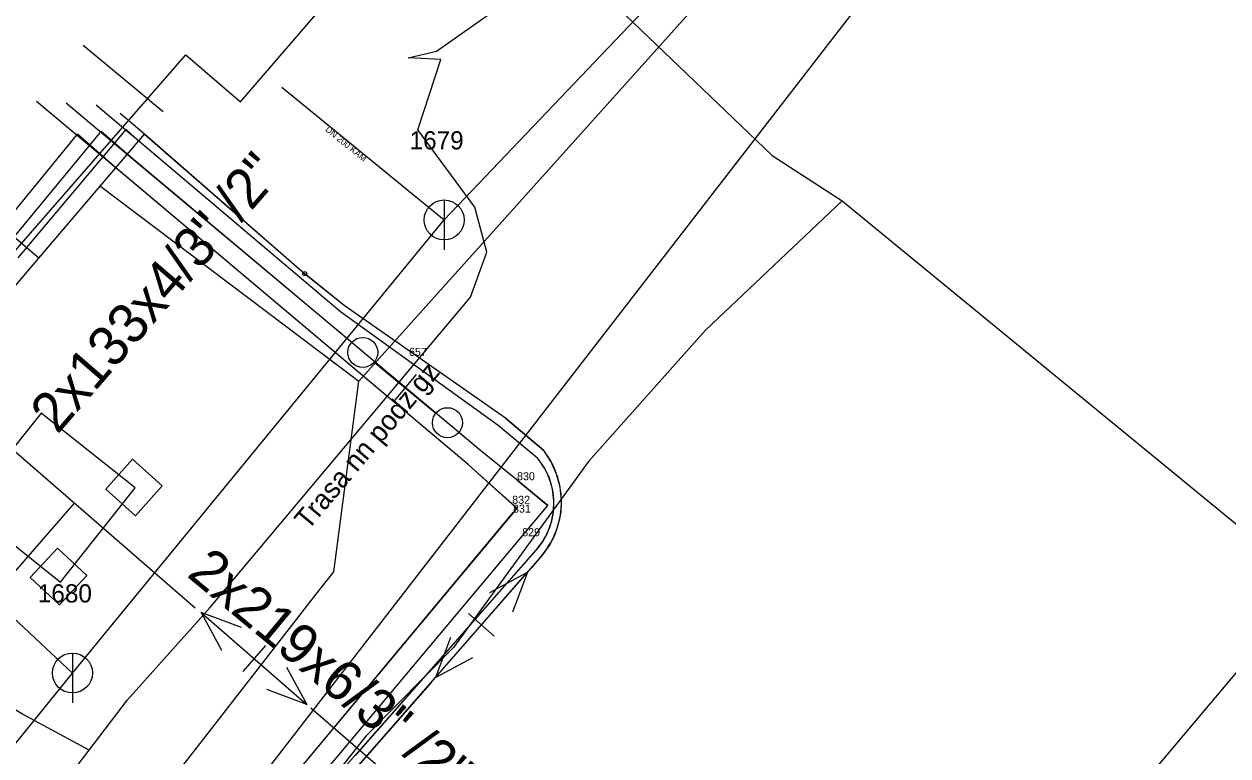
# Model space of a CAD drawing. Extents: x -494395 to -49419, y -1126982 to -112683.
# Drawn here: x -494321.11 to -494291.02, y -1126840.42 to -1126822.11 of the extents above; entities that cross this region are included whole.
import ezdxf

# ---------------------------------------------------------------- set-up
doc = ezdxf.new("R2010")
doc.units = 0
for name, color, linetype in [('Vrstva 1', 7, 'Continuous'), ('Vrstva 15', 7, 'Continuous'), ('Vrstva 17', 7, 'Continuous'), ('Vrstva 19', 7, 'Continuous'), ('Vrstva 20', 7, 'Continuous'), ('Vrstva 35', 7, 'Continuous'), ('Vrstva 45', 7, 'Continuous'), ('Vrstva 48', 7, 'Continuous'), ('Vrstva 49', 7, 'Continuous'), ('Vrstva 5', 7, 'Continuous'), ('Vrstva 9', 7, 'Continuous')]:
    doc.layers.add(name, color=color, linetype=linetype)

msp = doc.modelspace()

# ---------------------------------------------------------------- linework, layer by layer
at = {"layer": 'Vrstva 1'}
msp.add_line((-494319.22, -1126826.15), (-494312.74, -1126831.04), dxfattribs=at)
msp.add_lwpolyline([(-494360.93, -1126825.46), (-494336.61, -1126847.07), (-494335.52, -1126848.04), (-494331.63, -1126851.49), (-494328.43, -1126854.34), (-494326.87, -1126852.55), (-494322.66, -1126847.73), (-494316.57, -1126839.92), (-494313.81, -1126836.37), (-494313.37, -1126835.81), (-494312.74, -1126831.04), (-494296.98, -1126813.46), (-494295.26, -1126811.1), (-494294.71, -1126810.42), (-494294.273, -1126809.878)], dxfattribs=at)
at = {"layer": 'Vrstva 15'}
for p, q in [((-494310.61, -1126827.011), (-494304.84, -1126820.951)), ((-494314.667, -1126823.687), (-494310.61, -1126827.011)), ((-494319.9, -1126838.341), (-494310.61, -1126827.011)), ((-494323.18, -1126835.277), (-494319.9, -1126838.341)), ((-494334.61, -1126856.561), (-494319.9, -1126838.341))]:
    msp.add_line(p, q, dxfattribs=at)
at = {"layer": 'Vrstva 17'}
for p, q in [((-494310.61, -1126826.511), (-494310.61, -1126827.761)), ((-494319.9, -1126837.841), (-494319.9, -1126839.091))]:
    msp.add_line(p, q, dxfattribs=at)
for centre in [(-494310.61, -1126827.011), (-494319.9, -1126838.341)]:
    msp.add_circle(centre, 0.5, dxfattribs=at)
at = {"layer": 'Vrstva 20'}
for points in [[(-494292.524, -1126811.151), (-494292.619, -1126811.279), (-494299.712, -1126820.924), (-494325.277, -1126853.999), (-494328.623, -1126858.84)], [(-494316.901, -1126869.31), (-494312.976, -1126864.212), (-494296.263, -1126844.814), (-494282.714, -1126828.712), (-494277.399, -1126822.165)]]:
    msp.add_lwpolyline(points, dxfattribs=at)
at = {"layer": 'Vrstva 35'}
for points in [[(-494311.3, -1126816.88), (-494302.41, -1126825.4), (-494300.66, -1126826.53), (-494287.83, -1126837.07), (-494286.16, -1126837.53), (-494283.18, -1126840.13)], [(-494300.66, -1126826.53), (-494304.08, -1126829.77), (-494307, -1126833.05), (-494310.38, -1126837.7), (-494312.57, -1126839.92), (-494316.3, -1126844.63), (-494317.42, -1126846.17), (-494319.02, -1126847.69), (-494327.08, -1126857.66), (-494327.96, -1126857.89), (-494330.7, -1126861.76), (-494332.02, -1126864.51), (-494334.7, -1126868.68), (-494331.75, -1126870.74), (-494343.19, -1126889.21), (-494346.12, -1126887.28)]]:
    msp.add_lwpolyline(points, dxfattribs=at)
at = {"layer": 'Vrstva 45'}
for p, q in [((-494315.7, -1126824.06), (-494311.17, -1126818.8)), ((-494320.74, -1126827.97), (-494328.91, -1126821.01)), ((-494317.07, -1126822.88), (-494315.7, -1126824.06)), ((-494322.43, -1126828.11), (-494319.77, -1126824.87)), ((-494321.86, -1126828.04), (-494319.18, -1126824.8)), ((-494321.26, -1126827.96), (-494318.56, -1126824.75)), ((-494320.74, -1126827.97), (-494318.1, -1126824.87)), ((-494318.87, -1126825.66), (-494319.77, -1126824.87)), ((-494318.48, -1126825.41), (-494319.18, -1126824.8)), ((-494318.24, -1126825.04), (-494318.56, -1126824.75)), ((-494318.1, -1126824.87), (-494314.1, -1126828.35)), ((-494314.1, -1126828.36), (-494318.1, -1126824.87)), ((-494318.09, -1126824.87), (-494318.09, -1126824.87)), ((-494313.2, -1126829.31), (-494318.24, -1126825.04)), ((-494318.24, -1126825.04), (-494318.24, -1126825.04)), ((-494313.2, -1126829.31), (-494318.24, -1126825.04)), ((-494318.52, -1126825.38), (-494318.52, -1126825.38)), ((-494312.96, -1126830.04), (-494318.52, -1126825.38)), ((-494309.74, -1126832.74), (-494318.48, -1126825.41)), ((-494310.01, -1126833.13), (-494318.87, -1126825.66)), ((-494318.81, -1126825.72), (-494318.81, -1126825.72)), ((-494310.01, -1126833.13), (-494318.81, -1126825.72)), ((-494329.83, -1126838.63), (-494320.74, -1126827.97)), ((-494313.11, -1126829.15), (-494314.1, -1126828.35)), ((-494314.1, -1126828.35), (-494314.1, -1126828.35)), ((-494313.11, -1126829.15), (-494314.1, -1126828.36)), ((-494309.26, -1126832.15), (-494313.2, -1126829.31)), ((-494313.2, -1126829.31), (-494313.2, -1126829.31)), ((-494309.26, -1126832.15), (-494313.2, -1126829.31)), ((-494309.08, -1126831.97), (-494313.11, -1126829.15)), ((-494313.11, -1126829.15), (-494313.11, -1126829.15)), ((-494309.08, -1126831.97), (-494313.11, -1126829.15)), ((-494312.357, -1126830.564), (-494310.817, -1126831.84)), ((-494311.49, -1126830.41), (-494311.49, -1126830.41)), ((-494311.312, -1126830.872), (-494311.861, -1126831.534)), ((-494323.07, -1126831.3), (-494316.83, -1126836.71)), ((-494309.08, -1126831.97), (-494308.12, -1126832.78)), ((-494309.08, -1126831.97), (-494309.08, -1126831.97)), ((-494308.12, -1126832.78), (-494309.08, -1126831.97)), ((-494309.74, -1126832.74), (-494310.2, -1126832.36)), ((-494308.27, -1126832.98), (-494309.26, -1126832.15)), ((-494309.26, -1126832.15), (-494309.26, -1126832.15)), ((-494308.27, -1126832.98), (-494309.26, -1126832.15)), ((-494309.74, -1126832.74), (-494309.74, -1126832.74)), ((-494308.79, -1126833.52), (-494309.74, -1126832.74)), ((-494308.79, -1126833.52), (-494309.74, -1126832.74)), ((-494308.27, -1126832.98), (-494308.27, -1126832.98)), ((-494308.1, -1126833.21), (-494308.27, -1126832.98)), ((-494308.12, -1126832.78), (-494308.12, -1126832.78)), ((-494307.94, -1126833.06), (-494308.12, -1126832.78)), ((-494310.01, -1126833.13), (-494310.01, -1126833.13)), ((-494308.91, -1126834.11), (-494310.01, -1126833.13)), ((-494308.91, -1126834.12), (-494310.01, -1126833.13)), ((-494307.98, -1126833.47), (-494308.1, -1126833.21)), ((-494307.8, -1126833.37), (-494307.94, -1126833.06)), ((-494308.79, -1126833.52), (-494308.79, -1126833.52)), ((-494308.79, -1126833.52), (-494308.02, -1126834.15)), ((-494308.02, -1126834.15), (-494308.79, -1126833.52)), ((-494307.9, -1126833.74), (-494307.98, -1126833.47)), ((-494307.71, -1126833.69), (-494307.8, -1126833.37)), ((-494307.87, -1126834.03), (-494307.9, -1126833.74)), ((-494307.68, -1126834.03), (-494307.71, -1126833.69)), ((-494335.11, -1126851.71), (-494319.85, -1126834.09)), ((-494308.91, -1126834.11), (-494308.91, -1126834.11)), ((-494308.91, -1126834.11), (-494308.79, -1126834.22)), ((-494308.79, -1126834.22), (-494308.91, -1126834.12)), ((-494308.89, -1126834.33), (-494308.79, -1126834.22)), ((-494308.89, -1126834.34), (-494308.79, -1126834.22)), ((-494308.79, -1126834.22), (-494308.79, -1126834.22)), ((-494308.66, -1126834.92), (-494308.02, -1126834.15)), ((-494308.66, -1126834.92), (-494308.02, -1126834.15)), ((-494308.02, -1126834.15), (-494308.02, -1126834.15)), ((-494307.88, -1126834.3), (-494307.87, -1126834.03)), ((-494307.87, -1126834.03), (-494307.87, -1126834.03)), ((-494307.69, -1126834.32), (-494307.68, -1126834.03)), ((-494307.68, -1126834.03), (-494307.68, -1126834.03)), ((-494316.57, -1126843.56), (-494308.89, -1126834.33)), ((-494316.57, -1126843.56), (-494308.89, -1126834.34)), ((-494308.89, -1126834.33), (-494308.89, -1126834.33)), ((-494307.93, -1126834.56), (-494307.88, -1126834.3)), ((-494307.75, -1126834.61), (-494307.69, -1126834.32)), ((-494320.29, -1126834.6), (-494320.29, -1126834.6)), ((-494308.04, -1126834.86), (-494308.02, -1126834.82)), ((-494308.02, -1126834.82), (-494307.93, -1126834.56)), ((-494307.84, -1126834.88), (-494307.75, -1126834.61)), ((-494316.37, -1126844.12), (-494308.66, -1126834.92)), ((-494316.37, -1126844.12), (-494308.66, -1126834.92)), ((-494308.66, -1126834.92), (-494308.66, -1126834.92)), ((-494308.31, -1126835.27), (-494308.15, -1126835.06)), ((-494308.15, -1126835.06), (-494308.04, -1126834.86)), ((-494307.98, -1126835.15), (-494307.84, -1126834.88)), ((-494314.68, -1126842.49), (-494308.31, -1126835.27)), ((-494312.93, -1126840.85), (-494308.15, -1126835.39)), ((-494312.83, -1126840.4), (-494308.31, -1126835.27)), ((-494308.15, -1126835.38), (-494308.43, -1126835.71)), ((-494308.31, -1126835.27), (-494308.31, -1126835.27)), ((-494308.15, -1126835.39), (-494307.98, -1126835.15)), ((-494308.15, -1126835.38), (-494308.15, -1126835.38)), ((-494310.831, -1126838.457), (-494308.53, -1126835.82)), ((-494316.68, -1126836.832), (-494314.04, -1126839.13)), ((-494310.003, -1126836.857), (-494309.358, -1126837.422)), ((-494316.74, -1126837.01), (-494316.74, -1126837.01)), ((-494315.077, -1126837.656), (-494315.642, -1126838.306)), ((-494310.93, -1126838.57), (-494317.14, -1126845.66)), ((-494313.94, -1126839.21), (-494307.12, -1126845.12))]:
    msp.add_line(p, q, dxfattribs=at)
for points in [[(-494323.83, -1126830.64), (-494317.07, -1126822.88)], [(-494309.47, -1126836.327), (-494308.53, -1126835.82), (-494308.905, -1126836.819)], [(-494315.679, -1126837.205), (-494316.68, -1126836.832), (-494316.172, -1126837.771)], [(-494310.455, -1126837.456), (-494310.831, -1126838.457), (-494309.891, -1126837.95)], [(-494314.548, -1126838.191), (-494314.04, -1126839.13), (-494315.04, -1126838.756)]]:
    msp.add_lwpolyline(points, dxfattribs=at)
for centre, radius in [((-494314.096, -1126828.354), 0.05), ((-494312.644, -1126830.325), 0.375), ((-494310.528, -1126832.081), 0.375)]:
    msp.add_circle(centre, radius, dxfattribs=at)
for centre, radius, start, end in [((-494309.64, -1126834.103), 1.772, 2.3654, 39.3435), ((-494309.779, -1126834.066), 2.099, 0.9903, 37.7938), ((-494309.631, -1126834.103), 1.763, 318.5504, 2.3763), ((-494309.77, -1126834.059), 2.09, 320.8079, 0.8012)]:
    msp.add_arc(centre, radius, start, end, dxfattribs=at)
at = {"layer": 'Vrstva 48'}
for p, q in [((-494320.68, -1126831.84), (-494322.56, -1126834.19)), ((-494318.33, -1126833.71), (-494320.68, -1126831.84)), ((-494320.2, -1126836.07), (-494318.33, -1126833.71)), ((-494322.55, -1126834.19), (-494320.2, -1126836.07))]:
    msp.add_line(p, q, dxfattribs=at)
for points in [[(-494319.066, -1126833.741), (-494318.321, -1126834.407), (-494317.655, -1126833.661), (-494318.4, -1126832.995)], [(-494320.226, -1126836.636), (-494319.543, -1126835.906), (-494320.274, -1126835.223), (-494320.957, -1126835.953)]]:
    msp.add_lwpolyline(points, close=True, dxfattribs=at)
at = {"layer": 'Vrstva 49'}
for p, q in [((-494317.63, -1126824.31), (-494319.63, -1126822.65)), ((-494318.81, -1126825.72), (-494320.8, -1126824.05)), ((-494318.52, -1126825.38), (-494320.06, -1126824.09)), ((-494318.24, -1126825.04), (-494319.31, -1126824.14)), ((-494318.1, -1126824.87), (-494318.71, -1126824.35))]:
    msp.add_line(p, q, dxfattribs=at)
at = {"layer": 'Vrstva 5'}
for points in [[(-494311.512, -1126822.954), (-494310.798, -1126822.793), (-494308.474, -1126821.152), (-494307.171, -1126820.236), (-494302.377, -1126814.685), (-494297.3, -1126808.647), (-494296.842, -1126808.008)], [(-494319.485, -1126840.271), (-494318.524, -1126839.01), (-494316.478, -1126836.72), (-494309.952, -1126828.941), (-494309.546, -1126827.816), (-494309.841, -1126826.688), (-494311.271, -1126824.756), (-494310.692, -1126822.997), (-494311.512, -1126822.954)], [(-494319.485, -1126840.271), (-494321.148, -1126839.371), (-494323.139, -1126838.172), (-494325.83, -1126835.963), (-494326.623, -1126836.22)], [(-494334.819, -1126859.137), (-494334.405, -1126858.477), (-494332.038, -1126855.399), (-494327.363, -1126850.088), (-494321.788, -1126843.277), (-494320.277, -1126841.306), (-494319.485, -1126840.271)]]:
    msp.add_lwpolyline(points, dxfattribs=at)

# ---------------------------------------------------------------- texts
at = {"layer": 'Vrstva 19'}
msp.add_text('DN 200 KAM', height=0.1605, rotation=320.6795, dxfattribs=at).set_placement((-494313.595, -1126824.773))
for s, p in [('1679', (-494311.476, -1126825.247)), ('1680', (-494320.766, -1126836.577))]:
    msp.add_text(s, height=0.4549, dxfattribs=at).set_placement(p)
at = {"layer": 'Vrstva 49'}
for s, rotation, p in [('2x133x4/3" /2"', 49.1122, (-494320.275, -1126832.391)), ('2x219x6/3" /2"', 320.2343, (-494317.068, -1126835.907))]:
    msp.add_text(s, height=1, rotation=rotation, dxfattribs=at).set_placement(p)
for s, p in [('657', (-494311.49, -1126830.41)), ('830', (-494308.79, -1126833.52)), ('832', (-494308.91, -1126834.11)), ('831', (-494308.89, -1126834.33)), ('829', (-494308.66, -1126834.92))]:
    msp.add_text(s, height=0.2, dxfattribs=at).set_placement(p)
at = {"layer": 'Vrstva 9'}
msp.add_text('Trasa nn podz gz', height=0.5, rotation=50.0059, dxfattribs=at).set_placement((-494314.011, -1126834.79))

doc.saveas('drawing.dxf')
